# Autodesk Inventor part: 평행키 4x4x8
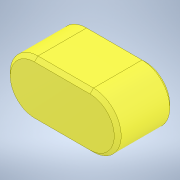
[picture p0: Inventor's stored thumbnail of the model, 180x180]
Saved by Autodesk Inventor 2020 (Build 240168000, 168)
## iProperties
Created: 2024-04
Part Number: 평행키 4x4x8
Material: 강철, 연강
Description: 평행 키
Document SubType Name: Modeling
Designer: oem
Density: 7.85 g/cm^3
Appearance: 기본값
Author: jhkim
Sending System: Autodesk Inventor 2025
Preprocessor: ST-DEVELOPER v20
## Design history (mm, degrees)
feature "Solid1"
node "솔리드1"
